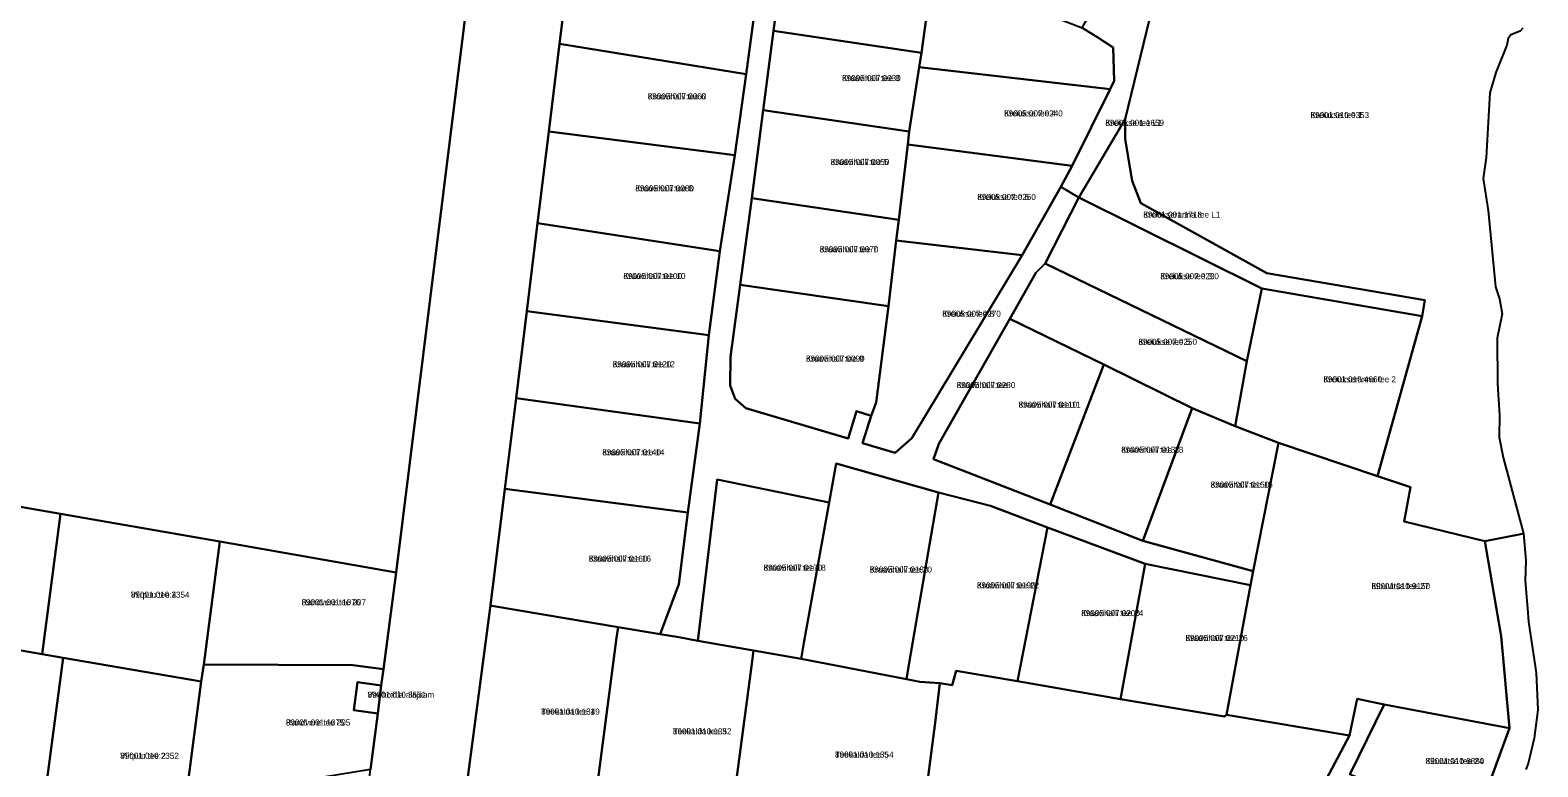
# Model space of a CAD drawing. Extents: x 526849 to 562296, y 6591741 to 6618546.
# Drawn here: x 551215.3 to 551588.6, y 6597126.2 to 6597308.8 of the extents above; entities that cross this region are included whole.
import ezdxf

# ---------------------------------------------------------------- set-up
doc = ezdxf.new("R2010")
doc.units = 0
for name, color, linetype in [('L_AADRESS', 7, 'Continuous'), ('PIIR', 7, 'Continuous'), ('TUNNUS', 7, 'Continuous')]:
    doc.layers.add(name, color=color, linetype=linetype)

msp = doc.modelspace()

# ---------------------------------------------------------------- linework, layer by layer
at = {"layer": 'PIIR'}
for points in [[(551159.19, 6597428.46), (551157.19, 6597364.86), (551327.65, 6597350), (551305.84, 6597174.43), (551262.18, 6597182.11), (551222.76, 6597188.93), (551183.34, 6597195.81), (551144.01, 6597202.58), (551128.73, 6597205.23), (551107.45, 6597232.01), (551098.85, 6597242.74), (551066.35, 6597283.61), (551064.54, 6597285.86), (551062.92, 6597287.79), (551000.17, 6597366.58), (550996.93, 6597374.7), (551063.31, 6597433.76), (551064.19, 6597430.76), (551123.43, 6597429.32)], [(551402.81, 6597334.73), (551404.84, 6597336.38), (551438.51, 6597324.53), (551438.73, 6597323.73), (551435.96, 6597303.19), (551399.34, 6597308.65)], [(551348.98, 6597326.82), (551395.52, 6597319.99), (551392.56, 6597297.89), (551346.35, 6597305.43)], [(551435.96, 6597303.19), (551438.73, 6597323.73), (551475.69, 6597309.35), (551479.63, 6597306.94), (551483.42, 6597304.52), (551483.68, 6597296.2), (551482.69, 6597294.15), (551435.4, 6597299.59)], [(551474.88, 6597267.34), (551470.43, 6597269.93), (551473.22, 6597275.2), (551482.69, 6597294.15), (551483.68, 6597296.2), (551483.42, 6597304.52), (551479.63, 6597306.94), (551475.69, 6597309.35), (551479.56, 6597316.2), (551492.52, 6597311.82), (551486.41, 6597286.7)], [(551399.34, 6597308.65), (551435.96, 6597303.19), (551435.4, 6597299.59), (551432.93, 6597283.64), (551396.73, 6597288.93)], [(551346.35, 6597305.43), (551392.56, 6597297.89), (551389.77, 6597277.84), (551343.67, 6597283.66)], [(551432.93, 6597283.64), (551435.4, 6597299.59), (551482.69, 6597294.15), (551473.22, 6597275.2), (551432.55, 6597280.43)], [(551396.73, 6597288.93), (551432.93, 6597283.64), (551432.55, 6597280.43), (551430.32, 6597261.82), (551393.91, 6597267.14)], [(551486.41, 6597286.7), (551486.4, 6597281.78), (551488.08, 6597271.48), (551490.25, 6597265.95), (551521.43, 6597248.59), (551560.6, 6597241.88), (551559.92, 6597237.94), (551520.21, 6597244.74), (551474.88, 6597267.34)], [(551343.67, 6597283.66), (551389.77, 6597277.84), (551385.99, 6597254.01), (551340.89, 6597260.98)], [(551430.32, 6597261.82), (551432.55, 6597280.43), (551473.22, 6597275.2), (551470.43, 6597269.93), (551460.85, 6597253), (551429.71, 6597256.68)], [(551474.88, 6597267.34), (551520.21, 6597244.74), (551516.52, 6597226.79), (551466.6, 6597250.94)], [(551393.91, 6597267.14), (551430.32, 6597261.82), (551429.71, 6597256.68), (551427.76, 6597240.36), (551391.06, 6597245.66)], [(551340.89, 6597260.98), (551385.99, 6597254.01), (551383.29, 6597233.23), (551338.21, 6597239.19)], [(551460.85, 6597253), (551433.58, 6597207.71), (551429.4, 6597204.06), (551421.33, 6597206.47), (551423.45, 6597213.24), (551424.76, 6597216.49), (551427.76, 6597240.36), (551429.71, 6597256.68)], [(551457.81, 6597237.29), (551464.29, 6597248.69), (551466.6, 6597250.94), (551516.52, 6597226.79), (551513.61, 6597210.66), (551502.98, 6597215.15), (551481.07, 6597225.9)], [(551389.83, 6597217.4), (551388.56, 6597220.76), (551388.69, 6597227.82), (551391.06, 6597245.66), (551427.76, 6597240.36), (551424.76, 6597216.49), (551423.45, 6597213.24), (551419.87, 6597214.4), (551417.76, 6597207.64), (551392.48, 6597215.13)], [(551098.85, 6597242.74), (551107.45, 6597232.01), (551099.97, 6597174.72), (551139.39, 6597167.88), (551178.8, 6597161.04), (551218.21, 6597154.19), (551223.39, 6597153.29), (551217.52, 6597108.33), (551211.83, 6597064.74), (551202.05, 6597067.07), (551207.61, 6597109.65), (551212.24, 6597145.09), (551177.5, 6597151.12), (551138.09, 6597157.96), (551098.68, 6597164.79), (551093.47, 6597124.92), (551087.55, 6597079.6), (551077.62, 6597080.68), (551084.05, 6597129.73), (551090.17, 6597176.42), (551096.2, 6597222.45)], [(551559.92, 6597237.94), (551548.87, 6597198.3), (551524.35, 6597206.52), (551513.61, 6597210.66), (551516.52, 6597226.79), (551520.21, 6597244.74)], [(551338.21, 6597239.19), (551383.29, 6597233.23), (551381.1, 6597211.32), (551335.55, 6597217.58)], [(551440.27, 6597206.29), (551457.81, 6597237.29), (551481.07, 6597225.9), (551467.81, 6597191.23), (551438.9, 6597202.44)], [(551481.07, 6597225.9), (551502.98, 6597215.15), (551490.72, 6597182.27), (551467.81, 6597191.23)], [(551335.55, 6597217.58), (551381.1, 6597211.32), (551378.11, 6597189.3), (551332.79, 6597195.11)], [(551502.98, 6597215.15), (551513.61, 6597210.66), (551524.35, 6597206.52), (551518.09, 6597174.74), (551490.72, 6597182.27)], [(551541.88, 6597134.03), (551511.44, 6597139.1), (551517.42, 6597171.3), (551518.09, 6597174.74), (551524.35, 6597206.52), (551548.87, 6597198.3), (551557.04, 6597195.52), (551555.44, 6597187.02), (551575.46, 6597182.17), (551579.49, 6597158.64), (551581.53, 6597135.8), (551550.49, 6597141.7), (551543.81, 6597143.06)], [(551406.75, 6597156.44), (551413.1, 6597191.75), (551414.84, 6597201.41), (551440.15, 6597194.21), (551432.91, 6597151.98), (551432.2, 6597147.96), (551412.6, 6597151.79), (551406.13, 6597152.99)], [(551381.01, 6597160.85), (551385.33, 6597197.41), (551413.1, 6597191.75), (551406.75, 6597156.44), (551406.13, 6597152.99), (551394.34, 6597155.05), (551380.6, 6597157.5)], [(551183.34, 6597195.81), (551222.76, 6597188.93), (551218.21, 6597154.19), (551178.8, 6597161.04)], [(551329.65, 6597169.57), (551332.79, 6597195.11), (551378.11, 6597189.3), (551375.87, 6597171.51), (551372.47, 6597162.41), (551371.23, 6597159.08), (551360.82, 6597160.89), (551329.56, 6597166.15), (551329.26, 6597166.39)], [(551443.55, 6597146.47), (551440.48, 6597147.01), (551435.55, 6597147.31), (551432.2, 6597147.96), (551432.91, 6597151.98), (551440.15, 6597194.21), (551453.06, 6597190.92), (551467.13, 6597185.59), (551459.68, 6597147.46), (551444.57, 6597150.01)], [(551218.21, 6597154.19), (551222.76, 6597188.93), (551262.18, 6597182.11), (551258.22, 6597151.64), (551257.62, 6597147.36), (551223.39, 6597153.29)], [(551467.13, 6597185.59), (551491.33, 6597176.57), (551485.2, 6597143.02), (551459.68, 6597147.46)], [(551295.17, 6597151.44), (551258.22, 6597151.64), (551262.18, 6597182.11), (551305.84, 6597174.43), (551302.76, 6597150.44)], [(551491.33, 6597176.57), (551517.42, 6597171.3), (551511.44, 6597139.1), (551510.96, 6597138.68), (551485.2, 6597143.02)], [(551329.26, 6597166.39), (551329.56, 6597166.15), (551360.82, 6597160.89), (551360.46, 6597158.17), (551354.45, 6597112.63), (551322.72, 6597116.82), (551329, 6597164.4)], [(551360.46, 6597158.17), (551360.82, 6597160.89), (551371.25, 6597159.13), (551375.83, 6597158.35), (551380.6, 6597157.5), (551394.34, 6597155.05), (551393.91, 6597151.78), (551388.42, 6597110.17), (551388.16, 6597108.19), (551354.45, 6597112.63)], [(551223.39, 6597153.29), (551257.62, 6597147.36), (551251.91, 6597103.73), (551217.52, 6597108.33)], [(551270.9, 6597122.3), (551254.25, 6597121.34), (551257.62, 6597147.36), (551258.22, 6597151.64), (551295.17, 6597151.44), (551302.76, 6597150.44), (551302.2, 6597146.43), (551296.29, 6597147.26), (551295.39, 6597140.28), (551301.33, 6597139.49), (551299.5, 6597125.57), (551279.83, 6597122.37)], [(551388.42, 6597110.17), (551393.91, 6597151.78), (551394.34, 6597155.05), (551406.13, 6597152.99), (551412.6, 6597151.79), (551432.2, 6597147.96), (551435.55, 6597147.31), (551440.48, 6597147.01), (551439.3, 6597137.13), (551437.39, 6597121.98), (551436.3, 6597113.26), (551434.91, 6597102.03), (551431.62, 6597102.46), (551400.06, 6597106.62), (551400.32, 6597108.6)], [(551496.61, 6597048.57), (551478.42, 6597058), (551429.04, 6597034.68), (551425.43, 6597032.99), (551429.86, 6597061.34), (551432.87, 6597085.7), (551434.88, 6597101.82), (551434.91, 6597102.03), (551436.3, 6597113.26), (551437.39, 6597121.98), (551439.3, 6597137.13), (551440.48, 6597147.01), (551443.55, 6597146.47), (551444.57, 6597150.01), (551459.68, 6597147.46), (551485.2, 6597143.02), (551510.96, 6597138.68), (551511.44, 6597139.1), (551541.88, 6597134.03)], [(551296.29, 6597147.26), (551302.2, 6597146.43), (551301.33, 6597139.49), (551295.39, 6597140.28)], [(551581.53, 6597135.8), (551572.83, 6597112.16), (551542.01, 6597124.37), (551550.49, 6597141.7)]]:
    msp.add_lwpolyline(points, close=True, dxfattribs=at)
for points in [[(551235.47, 6596628.55), (551239.4, 6596658.47), (551243.32, 6596688.28), (551247.22, 6596718.02), (551251.12, 6596747.71), (551255.03, 6596777.46), (551258.94, 6596807.25), (551262.85, 6596837.01), (551267.73, 6596874.18), (551269.99, 6596891.35), (551274.49, 6596928.19), (551277.26, 6596950.92), (551280.5, 6596977.49), (551284.83, 6597013.02), (551284.98, 6597014.21), (551287.55, 6597033.88), (551294.29, 6597085.5), (551299.5, 6597125.57), (551301.33, 6597139.49), (551302.2, 6597146.43), (551302.76, 6597150.44), (551305.84, 6597174.43), (551327.65, 6597350)], [(551402.81, 6597334.73), (551399.34, 6597308.65), (551396.73, 6597288.93), (551393.91, 6597267.14), (551391.06, 6597245.66), (551388.69, 6597227.82), (551388.56, 6597220.76), (551389.83, 6597217.4), (551392.48, 6597215.13), (551417.76, 6597207.64), (551419.87, 6597214.4), (551423.45, 6597213.24), (551421.33, 6597206.47), (551429.4, 6597204.06), (551433.58, 6597207.71), (551460.85, 6597253), (551470.43, 6597269.93), (551474.88, 6597267.34), (551466.6, 6597250.94), (551464.29, 6597248.69), (551457.81, 6597237.29), (551440.27, 6597206.29), (551438.9, 6597202.44), (551467.81, 6597191.23), (551490.72, 6597182.27), (551518.09, 6597174.74), (551517.42, 6597171.3), (551491.33, 6597176.57), (551467.13, 6597185.59), (551453.06, 6597190.92), (551440.15, 6597194.21), (551414.84, 6597201.41), (551413.1, 6597191.75), (551385.33, 6597197.41), (551381.01, 6597160.85), (551380.6, 6597157.5), (551375.83, 6597158.35), (551371.25, 6597159.13), (551372.47, 6597162.41), (551375.87, 6597171.51), (551378.11, 6597189.3), (551381.1, 6597211.32), (551383.29, 6597233.23), (551385.99, 6597254.01), (551389.77, 6597277.84), (551392.56, 6597297.89), (551395.52, 6597319.99)], [(551348.98, 6597326.82), (551346.35, 6597305.43), (551343.67, 6597283.66), (551340.89, 6597260.98), (551338.21, 6597239.19), (551335.55, 6597217.58), (551332.79, 6597195.11), (551329.65, 6597169.57), (551329.26, 6597166.39), (551329, 6597164.4), (551322.72, 6597116.82), (551321.42, 6597106.9), (551320.5, 6597099.96), (551315.08, 6597058.82), (551310.23, 6597022.05), (551307.4, 6597000.81), (551294.29, 6596892.32)], [(551584.8, 6597309.29), (551584.21, 6597308.56), (551581.84, 6597307.64), (551581.19, 6597306.7), (551580.88, 6597305.03), (551578.18, 6597298.3), (551576.7, 6597293.22), (551575.75, 6597277.24), (551575.01, 6597272.05), (551576.28, 6597264.12), (551578.08, 6597245.17), (551579.03, 6597242.21), (551579.75, 6597238.5), (551578.5, 6597232.47), (551578.58, 6597221.13), (551579.07, 6597213.42), (551579.01, 6597207.94), (551579.97, 6597202.9), (551584.96, 6597184.03), (551583.93, 6597183.83), (551575.46, 6597182.17), (551555.44, 6597187.02), (551557.04, 6597195.52), (551548.87, 6597198.3), (551559.92, 6597237.94), (551560.6, 6597241.88), (551521.43, 6597248.59), (551490.25, 6597265.95), (551488.08, 6597271.48), (551486.4, 6597281.78), (551486.41, 6597286.7), (551492.52, 6597311.82)], [(551572.83, 6597112.16), (551581.53, 6597135.8), (551579.49, 6597158.64), (551575.46, 6597182.17), (551583.93, 6597183.83), (551584.96, 6597184.03), (551585.6, 6597177.38), (551585.45, 6597172.33), (551585.97, 6597165.5), (551586.21, 6597162.2), (551588.13, 6597149.5), (551588.55, 6597140.41), (551587.6, 6597133.31), (551586.12, 6597127.06), (551585.59, 6597125.58)], [(551496.61, 6597048.57), (551541.88, 6597134.03), (551543.81, 6597143.06), (551550.49, 6597141.7), (551542.01, 6597124.37)]]:
    msp.add_lwpolyline(points, dxfattribs=at)

# ---------------------------------------------------------------- texts
at = {"layer": 'L_AADRESS'}
for s, p in [('Kraavihalli tee 3', (551416.28, 6597296.15)), ('Kraavihalli tee 6', (551368.17, 6597291.63)), ('Kreiukse tee 4', (551456.41, 6597287.4)), ('Kreiukse tee L1', (551481.48, 6597285.07)), ('Kreiukse tee 1', (551532.26, 6597286.99)), ('Kraavihalli tee 5', (551413.46, 6597275.38)), ('Kraavihalli tee 8', (551365.1, 6597268.84)), ('Kreiukse tee 6', (551449.76, 6597266.71)), ('Kreiukseranna tee L1', (551490.86, 6597262.32)), ('Kraavihalli tee 7', (551410.75, 6597253.75)), ('Kraavihalli tee 10', (551362.14, 6597247.11)), ('Kreiukse tee 3', (551495.08, 6597247.07)), ('Kreiukse tee 8', (551441.09, 6597237.76)), ('Kreiukse tee 5', (551489.65, 6597230.8)), ('Kraavihalli tee 12', (551359.49, 6597225.26)), ('Kraavihalli tee 9', (551407.35, 6597226.65)), ('Kreiukseranna tee 2', (551535.46, 6597221.52)), ('Kraavihalli tee', (551444.67, 6597220.1)), ('Kraavihalli tee 11', (551459.98, 6597215.24)), ('Kraavihalli tee 14', (551356.92, 6597203.44)), ('Kraavihalli tee 13', (551485.39, 6597204.07)), ('Kraavihalli tee 15', (551507.54, 6597195.43)), ('Kraavihalli tee 16', (551353.57, 6597177.09)), ('Kraavihalli tee 18', (551396.85, 6597174.84)), ('Kraavihalli tee 20', (551423.14, 6597174.39)), ('Kraavihalli tee 22', (551449.67, 6597170.47)), ('Kibuvitsa tee 27', (551547.36, 6597170.28)), ('Viirpuu tee 4', (551240.2, 6597168.15)), ('Randvere tee 207', (551282.46, 6597166.28)), ('Kraavihalli tee 24', (551475.5, 6597163.59)), ('Kraavihalli tee 26', (551501.31, 6597157.43)), ('Veehoidla alajaam', (551298.8, 6597143.37)), ('Teekalda tee 1', (551341.77, 6597139.2)), ('Randvere tee 205', (551278.57, 6597136.49)), ('Teekalda tee 3', (551374.4, 6597134.3)), ('Viirpuu tee 2', (551237.57, 6597128.24)), ('Teekalda tee 5', (551414.53, 6597128.54)), ('Kibuvitsa tee 24', (551560.76, 6597126.93))]:
    msp.add_text(s, height=1.5, dxfattribs=at).set_placement(p)
at = {"layer": 'TUNNUS'}
for s, p in [('89005:007:0030', (551416.28, 6597296.15)), ('89005:007:0060', (551368.17, 6597291.63)), ('89005:007:0240', (551456.41, 6597287.4)), ('89001:001:1659', (551481.48, 6597285.07)), ('89001:010:0353', (551532.26, 6597286.99)), ('89005:007:0050', (551413.46, 6597275.38)), ('89005:007:0080', (551365.1, 6597268.84)), ('89005:007:0260', (551449.76, 6597266.71)), ('89001:001:1718', (551490.86, 6597262.32)), ('89005:007:0070', (551410.75, 6597253.75)), ('89005:007:0100', (551362.14, 6597247.11)), ('89005:007:0230', (551495.08, 6597247.07)), ('89005:007:0270', (551441.09, 6597237.76)), ('89005:007:0250', (551489.65, 6597230.8)), ('89005:007:0120', (551359.49, 6597225.26)), ('89005:007:0090', (551407.35, 6597226.65)), ('89001:010:4660', (551535.46, 6597221.52)), ('89005:007:0280', (551444.67, 6597220.1)), ('89005:007:0110', (551459.98, 6597215.24)), ('89005:007:0140', (551356.92, 6597203.44)), ('89005:007:0130', (551485.39, 6597204.07)), ('89005:007:0150', (551507.54, 6597195.43)), ('89005:007:0160', (551353.57, 6597177.09)), ('89005:007:0170', (551396.85, 6597174.84)), ('89005:007:0180', (551423.14, 6597174.39)), ('89005:007:0190', (551449.67, 6597170.47)), ('89001:010:9150', (551547.36, 6597170.28)), ('89001:010:2354', (551240.2, 6597168.15)), ('89001:001:1076', (551282.46, 6597166.28)), ('89005:007:0200', (551475.5, 6597163.59)), ('89005:007:0210', (551501.31, 6597157.43)), ('89001:010:3551', (551298.8, 6597143.37)), ('89001:010:1349', (551341.77, 6597139.2)), ('89001:001:1075', (551278.57, 6597136.49)), ('89001:010:1352', (551374.4, 6597134.3)), ('89001:010:2352', (551237.57, 6597128.24)), ('89001:010:1354', (551414.53, 6597128.54)), ('89001:010:6880', (551560.76, 6597126.93))]:
    msp.add_text(s, height=1.5, dxfattribs=at).set_placement(p)

doc.saveas('drawing.dxf')
